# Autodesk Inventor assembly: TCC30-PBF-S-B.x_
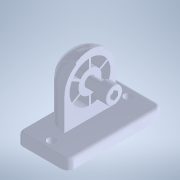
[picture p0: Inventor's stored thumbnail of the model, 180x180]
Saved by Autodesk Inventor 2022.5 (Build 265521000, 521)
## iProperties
Created: 2023-09
Part Number: TCC30-PBF-S-B.x_
Document SubType Name: Assembly
Designer: ImaoCorp
Sending System: SOLIDWORKS 2021-2021301
MC: AMD64
MC_MODEL: Intel64 Family 6 Model 60 Stepping 3, GenuineIntel
OS: Windows_NT
FRU: Parasolid Version 32.1, build 255,  1- 1-2021
FORMAT: text
GUISE: transmit
KEY: TCC30-PBF-S-B
FILE: TCC30-PBF-S-B.x_t
DATE: Fri Sep 15 15:37:04 2023
Author: ImaoCorp
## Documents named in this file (4)
- X:\14_SW2022-Inv2022\00_全2023-1023新製品(TCC)まで\t\tcc30-pbf-s-b\TCC30-PBF-S-B.iam
- X:\14_SW2022-Inv2022\00_全2023-1023新製品(TCC)まで\t\tcc30-pbf-s-b\TCC30-PBF-S-B_01.ipt
- X:\14_SW2022-Inv2022\00_全2023-1023新製品(TCC)まで\t\tcc30-pbf-s-b\TCC30-PBF-S-B_02.ipt
- X:\14_SW2022-Inv2022\00_全2023-1023新製品(TCC)まで\t\tcc30-pbf-s-b\TCC30-PBF-S-B_03.ipt
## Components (3 placed, 3 different names)
1. TCC30-PBF-S-B_01
2. TCC30-PBF-S-B_02
3. TCC30-PBF-S-B_03
